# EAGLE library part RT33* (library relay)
Power PCB Relay Inrush SCHRACK 1 pole 16 A, for inrush peak currents up to 80 A Source: http://www.schrack.com/.. 5825.pdf
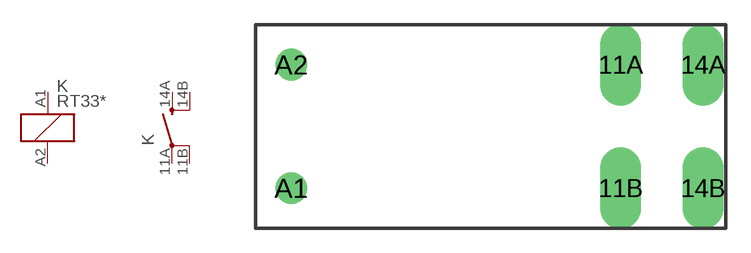
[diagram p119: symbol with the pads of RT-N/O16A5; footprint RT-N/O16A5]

Designator prefix K; gates 1=K 2=S-X2

## RT33K012 (MPN: RT33K012; OC_FARNELL: unknown; OC_NEWARK: 48M7964), RT33K024 (MPN: RT33K024; OC_FARNELL: unknown; OC_NEWARK: 48M7965), RT33K048 (MPN: RT33K048; OC_FARNELL: unknown; OC_NEWARK: 16R6370), RT33K060 (OC_FARNELL: unknown; OC_NEWARK: unknown), RT33L012 (MPN: RT33L012; OC_FARNELL: 1770614; OC_NEWARK: 74R4452), RT33L024 (MPN: RT33L024; OC_FARNELL: 1770616; OC_NEWARK: 74R4453), RT33L048 (MPN: RT33L048; OC_FARNELL: unknown; OC_NEWARK: 16R6377), RT33L060 (OC_FARNELL: unknown; OC_NEWARK: unknown)  [RT-N/O16A5]
11A  2:PA  pas
11B  2:PB  pas
14A  2:SA  pas
14B  2:SB  pas
A1  1:1  pas
A2  1:2  pas

## Footprint RT-N/O16A5 (pad centres in mm)
Power PCB Relay 1 pole 12 / 16 A, DC- or AC-coil SCHRACK 16 A, pinning 5mm Source: http://www.schrack.com/.. 5819.pdf
drill 1.3 pad 2.5 long: 11A 7.56,3.78; 11B 7.56,-3.78; 14A 12.6,3.78; 14B 12.6,-3.78
drill 1.3 round: A1 -12.6,-3.78; A2 -12.6,3.78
